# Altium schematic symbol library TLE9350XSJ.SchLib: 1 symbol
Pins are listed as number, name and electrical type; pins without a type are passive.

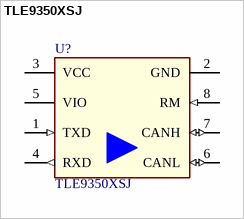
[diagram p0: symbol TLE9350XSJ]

## TLE9350XSJ
designator U?
High Speed CAN-Transceiver; Manufacturer: Infineon Technologies
pins: 1 TXD (in) "Transmit Data Input", 2 GND (power) "Ground", 3 VCC (power) "Transmitter Supply Voltage", 4 RXD (out) "Receive Data Output", 5 VIO (power) "Digital Supply Voltage", 6 CANL (io) "CAN Bus Low Level I/O", 7 CANH (io) "CAN Bus High Level I/O", 8 RM (in) "Receive-only Input"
